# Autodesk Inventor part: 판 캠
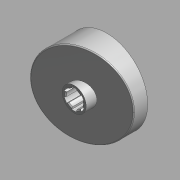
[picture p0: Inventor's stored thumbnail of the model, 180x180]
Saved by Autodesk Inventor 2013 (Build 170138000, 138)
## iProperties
Created: 2015-11
Part Number: 판 캠
Document SubType Name: 모델링
Designer: mdu
Material: 강철, 연강
Density: 1 g/cm^3
변환 표준: STEP AP214IS
파일 이름: C:\Users\SeoGD\Desktop\?쒗뿕\??stp
전처리기: Build: 253, Release: 2010 SP1 - Date: Wed 07/29/2009
전송 단위: 밀리미터
불확실성: 0.01
Author: mdu
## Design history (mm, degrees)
node "작업 평면4"
sketch "스케치1"
  geometry: C1 r 44.5 at (0, 0); 1 further point
  constraints: 1 centre point, 1 coincident
  dimensions: "d25" = 89 diameter of C1
extrude "돌출1" new body sketch "스케치1" distance "d1" = 40; taper "d2" = 0 deg
sketch "스케치2"
  geometry: L1 (-44.5, 15)-(44.5, 38.847); L2 (-44.5, 0)-(-44.5, 40) reference; L3 (-44.5, 40)-(44.5, 40) reference; L4 (44.5, 0)-(44.5, 40) reference; 1 further point
  constraints: 2 end point, 2 point on line
  dimensions: "d26" = 15 distance of L2.start L1.start; "d27" = 75 deg angle of L1 L2
extrude "돌출2" cut sketch "스케치2" stored distance "d5" = 40; taper "d6" = 0 deg
node "작업 평면1"
sketch "스케치3"
  geometry: C1 r 13 at (0, 0); 1 further point
  constraints: 1 centre point, 1 coincident
  dimensions: "d9" = 26 diameter of C1
extrude "돌출3" join sketch "스케치3" distance "d10" = 38; taper "d11" = 0 deg
hole "구멍1" diameter "d14" = 18; stored, may be unused: countersink angle "d18" = 90 deg, drill point angle "d20" = 118 deg; dims "d12" = 10, "d13" = 10, "d15" = 6, "d16" = 4, "d17" = 2, "d19" = 8
feature "쉘2" dims "d29" = 5
sketch "스케치6"
  geometry: C1 r 17.5 at (0, 0); C2 r 14 at (0, 0) reference; 1 further point
  constraints: 1 centre point, 1 coincident
  dimensions: "d28" = 35 diameter of C1
extrude "돌출4" join sketch "스케치6" stored distance "d30" = 38; taper "d31" = 0 deg
fillet "모깎기1" dims "d32" = 3
chamfer "모따기1" distance "d21" = 1; stored, may be unused: second distance "d22" = 2, angle "d23" = 45 deg
sketch "스케치7"
  geometry: L1 (-12.374, 12.374)-(-27.931, 27.931); A1 r 39.5 centre (0, 0) between (-27.931, 27.931) and (0, 39.5) reference; 2 further points
  constraints: 2 end point, 2 point on circle, 1 point on line, 1 vertical alignment, 2 other
  dimensions: "d33" = 45 deg dimension on point (0, 0) L1.start A1.end
feature "리브1" sketch "스케치7" dims "d34" = 5, "d35" = 1, "d36" = 0
fillet "모깎기2" dims "d37" = 3
sketch "스케치8"
  geometry: L1 (2.5, 10.712)-(2.5, 8.646); L2 (-2.5, 10.712)-(-2.5, 8.646); A1 r 11 centre (0, 0) between (2.5, 10.712) and (-2.5, 10.712); A2 r 9 centre (0, 0) between (2.5, 8.646) and (-2.5, 8.646) reference; 1 further point
  constraints: 4 end point, 4 point on circle, 2 parallel, 1 centre point, 1 coincident, 1 vertical
  dimensions: "d41" = 22 diameter of A1; "d42" = 5 distance between parallel lines of L1 L2
extrude "돌출5" cut sketch "스케치8" stored distance "d43" = 38; taper "d44" = 0 deg
fillet "모깎기3" dims "d48" = 1
node "솔리드1"
node "솔리드 본체"
node "곡면 본체"
pattern_circular "원형 패턴1" dims angle "d39" = 360 deg
pattern_circular "원형 패턴2" dims angle "d46" = 360 deg
node "솔리드2"
